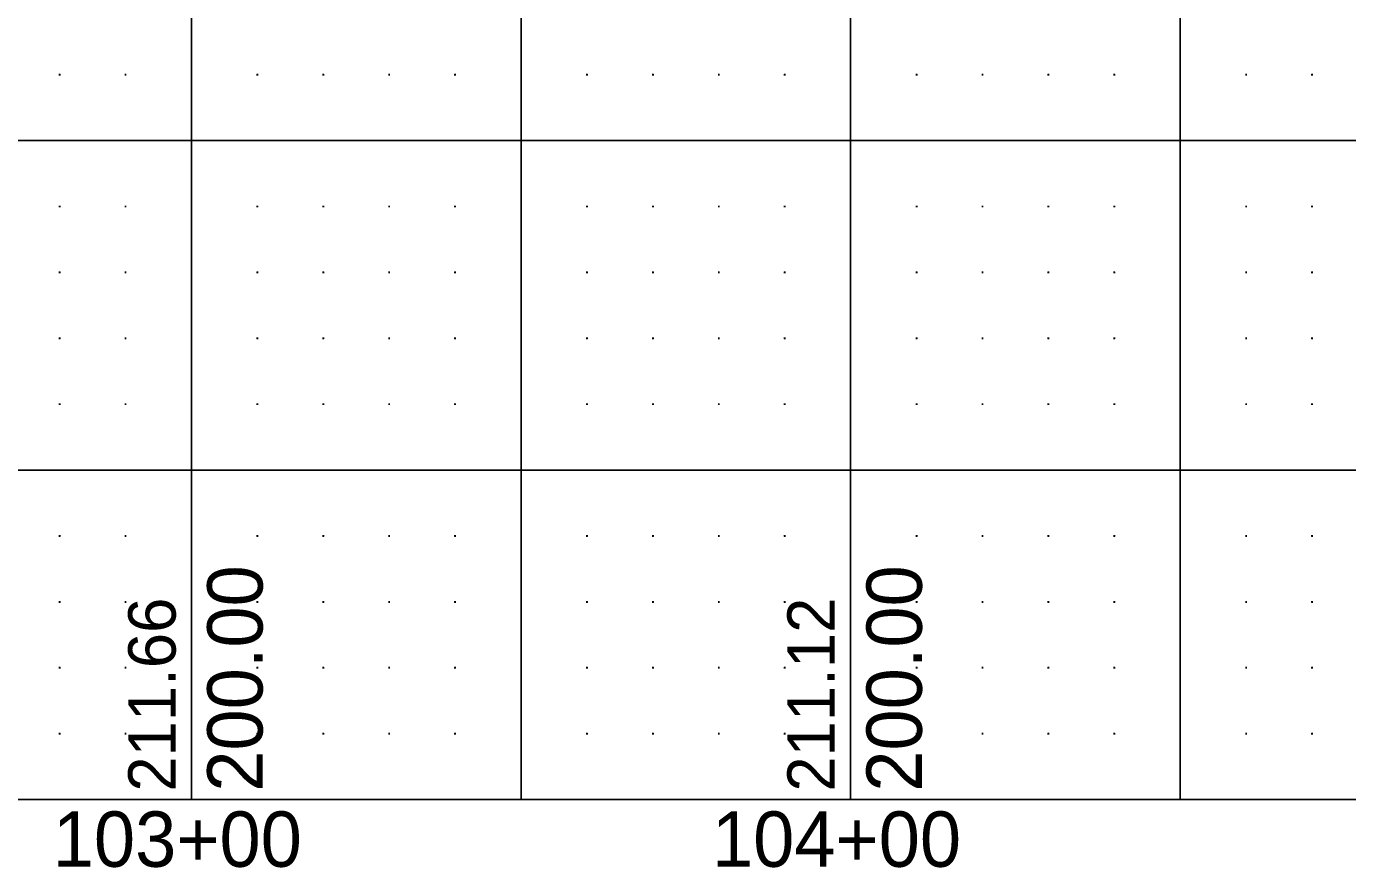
# Model space of a CAD drawing. Extents: x 471 to 2121, y 140 to 650.
# Drawn here: x 911 to 1111.4, y 139.7 to 267.3 of the extents above; entities that cross this region are included whole.
import ezdxf

# ---------------------------------------------------------------- set-up
doc = ezdxf.new("R2010")
doc.units = 0
for name, color, linetype in [('DSN_DRFT_Border Grid', 7, 'Continuous'), ('DSN_RDWY_Prof Annotation', 7, 'Continuous'), ('EX_Profile Annotation', 7, 'Continuous')]:
    doc.layers.add(name, color=color, linetype=linetype)

msp = doc.modelspace()

# ---------------------------------------------------------------- linework, layer by layer
at = {"layer": 'DSN_DRFT_Border Grid'}
for p, q in [((936.06, 150), (936.06, 650)), ((936.06, 150), (936.06, 650)), ((986.06, 150), (986.06, 650)), ((986.06, 150), (986.06, 650)), ((1036.06, 150), (1036.06, 650)), ((1036.06, 150), (1036.06, 650)), ((1086.06, 150), (1086.06, 650)), ((1086.06, 150), (1086.06, 650)), ((916.18, 260), (915.94, 260)), ((916.18, 260), (915.94, 260)), ((916.06, 260.12), (916.06, 259.88)), ((916.06, 260.12), (916.06, 259.88)), ((926.18, 260), (925.94, 260)), ((926.18, 260), (925.94, 260)), ((926.06, 260.12), (926.06, 259.88)), ((926.06, 260.12), (926.06, 259.88)), ((946.18, 260), (945.94, 260)), ((946.18, 260), (945.94, 260)), ((946.06, 260.12), (946.06, 259.88)), ((946.06, 260.12), (946.06, 259.88)), ((956.18, 260), (955.94, 260)), ((956.18, 260), (955.94, 260)), ((956.06, 260.12), (956.06, 259.88)), ((956.06, 260.12), (956.06, 259.88)), ((966.18, 260), (965.94, 260)), ((966.18, 260), (965.94, 260)), ((966.06, 260.12), (966.06, 259.88)), ((966.06, 260.12), (966.06, 259.88)), ((976.18, 260), (975.94, 260)), ((976.18, 260), (975.94, 260)), ((976.06, 260.12), (976.06, 259.88)), ((976.06, 260.12), (976.06, 259.88)), ((996.18, 260), (995.94, 260)), ((996.18, 260), (995.94, 260)), ((996.06, 260.12), (996.06, 259.88)), ((996.06, 260.12), (996.06, 259.88)), ((1006.18, 260), (1005.94, 260)), ((1006.18, 260), (1005.94, 260)), ((1006.06, 260.12), (1006.06, 259.88)), ((1006.06, 260.12), (1006.06, 259.88)), ((1016.18, 260), (1015.94, 260)), ((1016.18, 260), (1015.94, 260)), ((1016.06, 260.12), (1016.06, 259.88)), ((1016.06, 260.12), (1016.06, 259.88)), ((1026.18, 260), (1025.94, 260)), ((1026.18, 260), (1025.94, 260)), ((1026.06, 260.12), (1026.06, 259.88)), ((1026.06, 260.12), (1026.06, 259.88)), ((1046.18, 260), (1045.94, 260)), ((1046.18, 260), (1045.94, 260)), ((1046.06, 260.12), (1046.06, 259.88)), ((1046.06, 260.12), (1046.06, 259.88)), ((1056.18, 260), (1055.94, 260)), ((1056.18, 260), (1055.94, 260)), ((1056.06, 260.12), (1056.06, 259.88)), ((1056.06, 260.12), (1056.06, 259.88)), ((1066.18, 260), (1065.94, 260)), ((1066.18, 260), (1065.94, 260)), ((1066.06, 260.12), (1066.06, 259.88)), ((1066.06, 260.12), (1066.06, 259.88)), ((1076.18, 260), (1075.94, 260)), ((1076.18, 260), (1075.94, 260)), ((1076.06, 260.12), (1076.06, 259.88)), ((1076.06, 260.12), (1076.06, 259.88)), ((1096.18, 260), (1095.94, 260)), ((1096.18, 260), (1095.94, 260)), ((1096.06, 260.12), (1096.06, 259.88)), ((1096.06, 260.12), (1096.06, 259.88)), ((1106.18, 260), (1105.94, 260)), ((1106.18, 260), (1105.94, 260)), ((1106.06, 260.12), (1106.06, 259.88)), ((1106.06, 260.12), (1106.06, 259.88)), ((521.06, 250), (2071.06, 250)), ((521.06, 250), (2071.06, 250)), ((916.18, 240), (915.94, 240)), ((916.18, 240), (915.94, 240)), ((916.06, 240.12), (916.06, 239.88)), ((916.06, 240.12), (916.06, 239.88)), ((926.18, 240), (925.94, 240)), ((926.18, 240), (925.94, 240)), ((926.06, 240.12), (926.06, 239.88)), ((926.06, 240.12), (926.06, 239.88)), ((946.18, 240), (945.94, 240)), ((946.18, 240), (945.94, 240)), ((946.06, 240.12), (946.06, 239.88)), ((946.06, 240.12), (946.06, 239.88)), ((956.18, 240), (955.94, 240)), ((956.18, 240), (955.94, 240)), ((956.06, 240.12), (956.06, 239.88)), ((956.06, 240.12), (956.06, 239.88)), ((966.18, 240), (965.94, 240)), ((966.18, 240), (965.94, 240)), ((966.06, 240.12), (966.06, 239.88)), ((966.06, 240.12), (966.06, 239.88)), ((976.18, 240), (975.94, 240)), ((976.18, 240), (975.94, 240)), ((976.06, 240.12), (976.06, 239.88)), ((976.06, 240.12), (976.06, 239.88)), ((996.18, 240), (995.94, 240)), ((996.18, 240), (995.94, 240)), ((996.06, 240.12), (996.06, 239.88)), ((996.06, 240.12), (996.06, 239.88)), ((1006.18, 240), (1005.94, 240)), ((1006.18, 240), (1005.94, 240)), ((1006.06, 240.12), (1006.06, 239.88)), ((1006.06, 240.12), (1006.06, 239.88)), ((1016.18, 240), (1015.94, 240)), ((1016.18, 240), (1015.94, 240)), ((1016.06, 240.12), (1016.06, 239.88)), ((1016.06, 240.12), (1016.06, 239.88)), ((1026.18, 240), (1025.94, 240)), ((1026.18, 240), (1025.94, 240)), ((1026.06, 240.12), (1026.06, 239.88)), ((1026.06, 240.12), (1026.06, 239.88)), ((1046.18, 240), (1045.94, 240)), ((1046.18, 240), (1045.94, 240)), ((1046.06, 240.12), (1046.06, 239.88)), ((1046.06, 240.12), (1046.06, 239.88)), ((1056.18, 240), (1055.94, 240)), ((1056.18, 240), (1055.94, 240)), ((1056.06, 240.12), (1056.06, 239.88)), ((1056.06, 240.12), (1056.06, 239.88)), ((1066.18, 240), (1065.94, 240)), ((1066.18, 240), (1065.94, 240)), ((1066.06, 240.12), (1066.06, 239.88)), ((1066.06, 240.12), (1066.06, 239.88)), ((1076.18, 240), (1075.94, 240)), ((1076.18, 240), (1075.94, 240)), ((1076.06, 240.12), (1076.06, 239.88)), ((1076.06, 240.12), (1076.06, 239.88)), ((1096.18, 240), (1095.94, 240)), ((1096.18, 240), (1095.94, 240)), ((1096.06, 240.12), (1096.06, 239.88)), ((1096.06, 240.12), (1096.06, 239.88)), ((1106.18, 240), (1105.94, 240)), ((1106.18, 240), (1105.94, 240)), ((1106.06, 240.12), (1106.06, 239.88)), ((1106.06, 240.12), (1106.06, 239.88)), ((916.18, 230), (915.94, 230)), ((916.18, 230), (915.94, 230)), ((916.06, 230.12), (916.06, 229.88)), ((916.06, 230.12), (916.06, 229.88)), ((926.18, 230), (925.94, 230)), ((926.18, 230), (925.94, 230)), ((926.06, 230.12), (926.06, 229.88)), ((926.06, 230.12), (926.06, 229.88)), ((946.18, 230), (945.94, 230)), ((946.18, 230), (945.94, 230)), ((946.06, 230.12), (946.06, 229.88)), ((946.06, 230.12), (946.06, 229.88)), ((956.18, 230), (955.94, 230)), ((956.18, 230), (955.94, 230)), ((956.06, 230.12), (956.06, 229.88)), ((956.06, 230.12), (956.06, 229.88)), ((966.18, 230), (965.94, 230)), ((966.18, 230), (965.94, 230)), ((966.06, 230.12), (966.06, 229.88)), ((966.06, 230.12), (966.06, 229.88)), ((976.18, 230), (975.94, 230)), ((976.18, 230), (975.94, 230)), ((976.06, 230.12), (976.06, 229.88)), ((976.06, 230.12), (976.06, 229.88)), ((996.18, 230), (995.94, 230)), ((996.18, 230), (995.94, 230)), ((996.06, 230.12), (996.06, 229.88)), ((996.06, 230.12), (996.06, 229.88)), ((1006.18, 230), (1005.94, 230)), ((1006.18, 230), (1005.94, 230)), ((1006.06, 230.12), (1006.06, 229.88)), ((1006.06, 230.12), (1006.06, 229.88)), ((1016.18, 230), (1015.94, 230)), ((1016.18, 230), (1015.94, 230)), ((1016.06, 230.12), (1016.06, 229.88)), ((1016.06, 230.12), (1016.06, 229.88)), ((1026.18, 230), (1025.94, 230)), ((1026.18, 230), (1025.94, 230)), ((1026.06, 230.12), (1026.06, 229.88)), ((1026.06, 230.12), (1026.06, 229.88)), ((1046.18, 230), (1045.94, 230)), ((1046.18, 230), (1045.94, 230)), ((1046.06, 230.12), (1046.06, 229.88)), ((1046.06, 230.12), (1046.06, 229.88)), ((1056.18, 230), (1055.94, 230)), ((1056.18, 230), (1055.94, 230)), ((1056.06, 230.12), (1056.06, 229.88)), ((1056.06, 230.12), (1056.06, 229.88)), ((1066.18, 230), (1065.94, 230)), ((1066.18, 230), (1065.94, 230)), ((1066.06, 230.12), (1066.06, 229.88)), ((1066.06, 230.12), (1066.06, 229.88)), ((1076.18, 230), (1075.94, 230)), ((1076.18, 230), (1075.94, 230)), ((1076.06, 230.12), (1076.06, 229.88)), ((1076.06, 230.12), (1076.06, 229.88)), ((1096.18, 230), (1095.94, 230)), ((1096.18, 230), (1095.94, 230)), ((1096.06, 230.12), (1096.06, 229.88)), ((1096.06, 230.12), (1096.06, 229.88)), ((1106.18, 230), (1105.94, 230)), ((1106.18, 230), (1105.94, 230)), ((1106.06, 230.12), (1106.06, 229.88)), ((1106.06, 230.12), (1106.06, 229.88)), ((916.18, 220), (915.94, 220)), ((916.18, 220), (915.94, 220)), ((916.06, 220.12), (916.06, 219.88)), ((916.06, 220.12), (916.06, 219.88)), ((926.18, 220), (925.94, 220)), ((926.18, 220), (925.94, 220)), ((926.06, 220.12), (926.06, 219.88)), ((926.06, 220.12), (926.06, 219.88)), ((946.18, 220), (945.94, 220)), ((946.18, 220), (945.94, 220)), ((946.06, 220.12), (946.06, 219.88)), ((946.06, 220.12), (946.06, 219.88)), ((956.18, 220), (955.94, 220)), ((956.18, 220), (955.94, 220)), ((956.06, 220.12), (956.06, 219.88)), ((956.06, 220.12), (956.06, 219.88)), ((966.18, 220), (965.94, 220)), ((966.18, 220), (965.94, 220)), ((966.06, 220.12), (966.06, 219.88)), ((966.06, 220.12), (966.06, 219.88)), ((976.18, 220), (975.94, 220)), ((976.18, 220), (975.94, 220)), ((976.06, 220.12), (976.06, 219.88)), ((976.06, 220.12), (976.06, 219.88)), ((996.18, 220), (995.94, 220)), ((996.18, 220), (995.94, 220)), ((996.06, 220.12), (996.06, 219.88)), ((996.06, 220.12), (996.06, 219.88)), ((1006.18, 220), (1005.94, 220)), ((1006.18, 220), (1005.94, 220)), ((1006.06, 220.12), (1006.06, 219.88)), ((1006.06, 220.12), (1006.06, 219.88)), ((1016.18, 220), (1015.94, 220)), ((1016.18, 220), (1015.94, 220)), ((1016.06, 220.12), (1016.06, 219.88)), ((1016.06, 220.12), (1016.06, 219.88)), ((1026.18, 220), (1025.94, 220)), ((1026.18, 220), (1025.94, 220)), ((1026.06, 220.12), (1026.06, 219.88)), ((1026.06, 220.12), (1026.06, 219.88)), ((1046.18, 220), (1045.94, 220)), ((1046.18, 220), (1045.94, 220)), ((1046.06, 220.12), (1046.06, 219.88)), ((1046.06, 220.12), (1046.06, 219.88)), ((1056.18, 220), (1055.94, 220)), ((1056.18, 220), (1055.94, 220)), ((1056.06, 220.12), (1056.06, 219.88)), ((1056.06, 220.12), (1056.06, 219.88)), ((1066.18, 220), (1065.94, 220)), ((1066.18, 220), (1065.94, 220)), ((1066.06, 220.12), (1066.06, 219.88)), ((1066.06, 220.12), (1066.06, 219.88)), ((1076.18, 220), (1075.94, 220)), ((1076.18, 220), (1075.94, 220)), ((1076.06, 220.12), (1076.06, 219.88)), ((1076.06, 220.12), (1076.06, 219.88)), ((1096.18, 220), (1095.94, 220)), ((1096.18, 220), (1095.94, 220)), ((1096.06, 220.12), (1096.06, 219.88)), ((1096.06, 220.12), (1096.06, 219.88)), ((1106.18, 220), (1105.94, 220)), ((1106.18, 220), (1105.94, 220)), ((1106.06, 220.12), (1106.06, 219.88)), ((1106.06, 220.12), (1106.06, 219.88)), ((916.18, 210), (915.94, 210)), ((916.18, 210), (915.94, 210)), ((916.06, 210.12), (916.06, 209.88)), ((916.06, 210.12), (916.06, 209.88)), ((926.18, 210), (925.94, 210)), ((926.18, 210), (925.94, 210)), ((926.06, 210.12), (926.06, 209.88)), ((926.06, 210.12), (926.06, 209.88)), ((946.18, 210), (945.94, 210)), ((946.18, 210), (945.94, 210)), ((946.06, 210.12), (946.06, 209.88)), ((946.06, 210.12), (946.06, 209.88)), ((956.18, 210), (955.94, 210)), ((956.18, 210), (955.94, 210)), ((956.06, 210.12), (956.06, 209.88)), ((956.06, 210.12), (956.06, 209.88)), ((966.18, 210), (965.94, 210)), ((966.18, 210), (965.94, 210)), ((966.06, 210.12), (966.06, 209.88)), ((966.06, 210.12), (966.06, 209.88)), ((976.18, 210), (975.94, 210)), ((976.18, 210), (975.94, 210)), ((976.06, 210.12), (976.06, 209.88)), ((976.06, 210.12), (976.06, 209.88)), ((996.18, 210), (995.94, 210)), ((996.18, 210), (995.94, 210)), ((996.06, 210.12), (996.06, 209.88)), ((996.06, 210.12), (996.06, 209.88)), ((1006.18, 210), (1005.94, 210)), ((1006.18, 210), (1005.94, 210)), ((1006.06, 210.12), (1006.06, 209.88)), ((1006.06, 210.12), (1006.06, 209.88)), ((1016.18, 210), (1015.94, 210)), ((1016.18, 210), (1015.94, 210)), ((1016.06, 210.12), (1016.06, 209.88)), ((1016.06, 210.12), (1016.06, 209.88)), ((1026.18, 210), (1025.94, 210)), ((1026.18, 210), (1025.94, 210)), ((1026.06, 210.12), (1026.06, 209.88)), ((1026.06, 210.12), (1026.06, 209.88)), ((1046.18, 210), (1045.94, 210)), ((1046.18, 210), (1045.94, 210)), ((1046.06, 210.12), (1046.06, 209.88)), ((1046.06, 210.12), (1046.06, 209.88)), ((1056.18, 210), (1055.94, 210)), ((1056.18, 210), (1055.94, 210)), ((1056.06, 210.12), (1056.06, 209.88)), ((1056.06, 210.12), (1056.06, 209.88)), ((1066.18, 210), (1065.94, 210)), ((1066.18, 210), (1065.94, 210)), ((1066.06, 210.12), (1066.06, 209.88)), ((1066.06, 210.12), (1066.06, 209.88)), ((1076.18, 210), (1075.94, 210)), ((1076.18, 210), (1075.94, 210)), ((1076.06, 210.12), (1076.06, 209.88)), ((1076.06, 210.12), (1076.06, 209.88)), ((1096.18, 210), (1095.94, 210)), ((1096.18, 210), (1095.94, 210)), ((1096.06, 210.12), (1096.06, 209.88)), ((1096.06, 210.12), (1096.06, 209.88)), ((1106.18, 210), (1105.94, 210)), ((1106.18, 210), (1105.94, 210)), ((1106.06, 210.12), (1106.06, 209.88)), ((1106.06, 210.12), (1106.06, 209.88)), ((521.06, 200), (2071.06, 200)), ((521.06, 200), (2071.06, 200)), ((916.18, 190), (915.94, 190)), ((916.18, 190), (915.94, 190)), ((916.06, 190.12), (916.06, 189.88)), ((916.06, 190.12), (916.06, 189.88)), ((926.18, 190), (925.94, 190)), ((926.18, 190), (925.94, 190)), ((926.06, 190.12), (926.06, 189.88)), ((926.06, 190.12), (926.06, 189.88)), ((946.18, 190), (945.94, 190)), ((946.18, 190), (945.94, 190)), ((946.06, 190.12), (946.06, 189.88)), ((946.06, 190.12), (946.06, 189.88)), ((956.18, 190), (955.94, 190)), ((956.18, 190), (955.94, 190)), ((956.06, 190.12), (956.06, 189.88)), ((956.06, 190.12), (956.06, 189.88)), ((966.18, 190), (965.94, 190)), ((966.18, 190), (965.94, 190)), ((966.06, 190.12), (966.06, 189.88)), ((966.06, 190.12), (966.06, 189.88)), ((976.18, 190), (975.94, 190)), ((976.18, 190), (975.94, 190)), ((976.06, 190.12), (976.06, 189.88)), ((976.06, 190.12), (976.06, 189.88)), ((996.18, 190), (995.94, 190)), ((996.18, 190), (995.94, 190)), ((996.06, 190.12), (996.06, 189.88)), ((996.06, 190.12), (996.06, 189.88)), ((1006.18, 190), (1005.94, 190)), ((1006.18, 190), (1005.94, 190)), ((1006.06, 190.12), (1006.06, 189.88)), ((1006.06, 190.12), (1006.06, 189.88)), ((1016.18, 190), (1015.94, 190)), ((1016.18, 190), (1015.94, 190)), ((1016.06, 190.12), (1016.06, 189.88)), ((1016.06, 190.12), (1016.06, 189.88)), ((1026.18, 190), (1025.94, 190)), ((1026.18, 190), (1025.94, 190)), ((1026.06, 190.12), (1026.06, 189.88)), ((1026.06, 190.12), (1026.06, 189.88)), ((1046.18, 190), (1045.94, 190)), ((1046.18, 190), (1045.94, 190)), ((1046.06, 190.12), (1046.06, 189.88)), ((1046.06, 190.12), (1046.06, 189.88)), ((1056.18, 190), (1055.94, 190)), ((1056.18, 190), (1055.94, 190)), ((1056.06, 190.12), (1056.06, 189.88)), ((1056.06, 190.12), (1056.06, 189.88)), ((1066.18, 190), (1065.94, 190)), ((1066.18, 190), (1065.94, 190)), ((1066.06, 190.12), (1066.06, 189.88)), ((1066.06, 190.12), (1066.06, 189.88)), ((1076.18, 190), (1075.94, 190)), ((1076.18, 190), (1075.94, 190)), ((1076.06, 190.12), (1076.06, 189.88)), ((1076.06, 190.12), (1076.06, 189.88)), ((1096.18, 190), (1095.94, 190)), ((1096.18, 190), (1095.94, 190)), ((1096.06, 190.12), (1096.06, 189.88)), ((1096.06, 190.12), (1096.06, 189.88)), ((1106.18, 190), (1105.94, 190)), ((1106.18, 190), (1105.94, 190)), ((1106.06, 190.12), (1106.06, 189.88)), ((1106.06, 190.12), (1106.06, 189.88)), ((916.18, 180), (915.94, 180)), ((916.18, 180), (915.94, 180)), ((916.06, 180.12), (916.06, 179.88)), ((916.06, 180.12), (916.06, 179.88)), ((926.18, 180), (925.94, 180)), ((926.18, 180), (925.94, 180)), ((926.06, 180.12), (926.06, 179.88)), ((926.06, 180.12), (926.06, 179.88)), ((946.18, 180), (945.94, 180)), ((946.18, 180), (945.94, 180)), ((946.06, 180.12), (946.06, 179.88)), ((946.06, 180.12), (946.06, 179.88)), ((956.18, 180), (955.94, 180)), ((956.18, 180), (955.94, 180)), ((956.06, 180.12), (956.06, 179.88)), ((956.06, 180.12), (956.06, 179.88)), ((966.18, 180), (965.94, 180)), ((966.18, 180), (965.94, 180)), ((966.06, 180.12), (966.06, 179.88)), ((966.06, 180.12), (966.06, 179.88)), ((976.18, 180), (975.94, 180)), ((976.18, 180), (975.94, 180)), ((976.06, 180.12), (976.06, 179.88)), ((976.06, 180.12), (976.06, 179.88)), ((996.18, 180), (995.94, 180)), ((996.18, 180), (995.94, 180)), ((996.06, 180.12), (996.06, 179.88)), ((996.06, 180.12), (996.06, 179.88)), ((1006.18, 180), (1005.94, 180)), ((1006.18, 180), (1005.94, 180)), ((1006.06, 180.12), (1006.06, 179.88)), ((1006.06, 180.12), (1006.06, 179.88)), ((1016.18, 180), (1015.94, 180)), ((1016.18, 180), (1015.94, 180)), ((1016.06, 180.12), (1016.06, 179.88)), ((1016.06, 180.12), (1016.06, 179.88)), ((1026.18, 180), (1025.94, 180)), ((1026.18, 180), (1025.94, 180)), ((1026.06, 180.12), (1026.06, 179.88)), ((1026.06, 180.12), (1026.06, 179.88)), ((1046.18, 180), (1045.94, 180)), ((1046.18, 180), (1045.94, 180)), ((1046.06, 180.12), (1046.06, 179.88)), ((1046.06, 180.12), (1046.06, 179.88)), ((1056.18, 180), (1055.94, 180)), ((1056.18, 180), (1055.94, 180)), ((1056.06, 180.12), (1056.06, 179.88)), ((1056.06, 180.12), (1056.06, 179.88)), ((1066.18, 180), (1065.94, 180)), ((1066.18, 180), (1065.94, 180)), ((1066.06, 180.12), (1066.06, 179.88)), ((1066.06, 180.12), (1066.06, 179.88)), ((1076.18, 180), (1075.94, 180)), ((1076.18, 180), (1075.94, 180)), ((1076.06, 180.12), (1076.06, 179.88)), ((1076.06, 180.12), (1076.06, 179.88)), ((1096.18, 180), (1095.94, 180)), ((1096.18, 180), (1095.94, 180)), ((1096.06, 180.12), (1096.06, 179.88)), ((1096.06, 180.12), (1096.06, 179.88)), ((1106.18, 180), (1105.94, 180)), ((1106.18, 180), (1105.94, 180)), ((1106.06, 180.12), (1106.06, 179.88)), ((1106.06, 180.12), (1106.06, 179.88)), ((916.18, 170), (915.94, 170)), ((916.18, 170), (915.94, 170)), ((916.06, 170.12), (916.06, 169.88)), ((916.06, 170.12), (916.06, 169.88)), ((926.18, 170), (925.94, 170)), ((926.18, 170), (925.94, 170)), ((926.06, 170.12), (926.06, 169.88)), ((926.06, 170.12), (926.06, 169.88)), ((946.18, 170), (945.94, 170)), ((946.18, 170), (945.94, 170)), ((946.06, 170.12), (946.06, 169.88)), ((946.06, 170.12), (946.06, 169.88)), ((956.18, 170), (955.94, 170)), ((956.18, 170), (955.94, 170)), ((956.06, 170.12), (956.06, 169.88)), ((956.06, 170.12), (956.06, 169.88)), ((966.18, 170), (965.94, 170)), ((966.18, 170), (965.94, 170)), ((966.06, 170.12), (966.06, 169.88)), ((966.06, 170.12), (966.06, 169.88)), ((976.18, 170), (975.94, 170)), ((976.18, 170), (975.94, 170)), ((976.06, 170.12), (976.06, 169.88)), ((976.06, 170.12), (976.06, 169.88)), ((996.18, 170), (995.94, 170)), ((996.18, 170), (995.94, 170)), ((996.06, 170.12), (996.06, 169.88)), ((996.06, 170.12), (996.06, 169.88)), ((1006.18, 170), (1005.94, 170)), ((1006.18, 170), (1005.94, 170)), ((1006.06, 170.12), (1006.06, 169.88)), ((1006.06, 170.12), (1006.06, 169.88)), ((1016.18, 170), (1015.94, 170)), ((1016.18, 170), (1015.94, 170)), ((1016.06, 170.12), (1016.06, 169.88)), ((1016.06, 170.12), (1016.06, 169.88)), ((1026.18, 170), (1025.94, 170)), ((1026.18, 170), (1025.94, 170)), ((1026.06, 170.12), (1026.06, 169.88)), ((1026.06, 170.12), (1026.06, 169.88)), ((1046.18, 170), (1045.94, 170)), ((1046.18, 170), (1045.94, 170)), ((1046.06, 170.12), (1046.06, 169.88)), ((1046.06, 170.12), (1046.06, 169.88)), ((1056.18, 170), (1055.94, 170)), ((1056.18, 170), (1055.94, 170)), ((1056.06, 170.12), (1056.06, 169.88)), ((1056.06, 170.12), (1056.06, 169.88)), ((1066.18, 170), (1065.94, 170)), ((1066.18, 170), (1065.94, 170)), ((1066.06, 170.12), (1066.06, 169.88)), ((1066.06, 170.12), (1066.06, 169.88)), ((1076.18, 170), (1075.94, 170)), ((1076.18, 170), (1075.94, 170)), ((1076.06, 170.12), (1076.06, 169.88)), ((1076.06, 170.12), (1076.06, 169.88)), ((1096.18, 170), (1095.94, 170)), ((1096.18, 170), (1095.94, 170)), ((1096.06, 170.12), (1096.06, 169.88)), ((1096.06, 170.12), (1096.06, 169.88)), ((1106.18, 170), (1105.94, 170)), ((1106.18, 170), (1105.94, 170)), ((1106.06, 170.12), (1106.06, 169.88)), ((1106.06, 170.12), (1106.06, 169.88)), ((916.18, 160), (915.94, 160)), ((916.18, 160), (915.94, 160)), ((916.06, 160.12), (916.06, 159.88)), ((916.06, 160.12), (916.06, 159.88)), ((926.18, 160), (925.94, 160)), ((926.18, 160), (925.94, 160)), ((926.06, 160.12), (926.06, 159.88)), ((926.06, 160.12), (926.06, 159.88)), ((946.18, 160), (945.94, 160)), ((946.18, 160), (945.94, 160)), ((946.06, 160.12), (946.06, 159.88)), ((946.06, 160.12), (946.06, 159.88)), ((956.18, 160), (955.94, 160)), ((956.18, 160), (955.94, 160)), ((956.06, 160.12), (956.06, 159.88)), ((956.06, 160.12), (956.06, 159.88)), ((966.18, 160), (965.94, 160)), ((966.18, 160), (965.94, 160)), ((966.06, 160.12), (966.06, 159.88)), ((966.06, 160.12), (966.06, 159.88)), ((976.18, 160), (975.94, 160)), ((976.18, 160), (975.94, 160)), ((976.06, 160.12), (976.06, 159.88)), ((976.06, 160.12), (976.06, 159.88)), ((996.18, 160), (995.94, 160)), ((996.18, 160), (995.94, 160)), ((996.06, 160.12), (996.06, 159.88)), ((996.06, 160.12), (996.06, 159.88)), ((1006.18, 160), (1005.94, 160)), ((1006.18, 160), (1005.94, 160)), ((1006.06, 160.12), (1006.06, 159.88)), ((1006.06, 160.12), (1006.06, 159.88)), ((1016.18, 160), (1015.94, 160)), ((1016.18, 160), (1015.94, 160)), ((1016.06, 160.12), (1016.06, 159.88)), ((1016.06, 160.12), (1016.06, 159.88)), ((1026.18, 160), (1025.94, 160)), ((1026.18, 160), (1025.94, 160)), ((1026.06, 160.12), (1026.06, 159.88)), ((1026.06, 160.12), (1026.06, 159.88)), ((1046.18, 160), (1045.94, 160)), ((1046.18, 160), (1045.94, 160)), ((1046.06, 160.12), (1046.06, 159.88)), ((1046.06, 160.12), (1046.06, 159.88)), ((1056.18, 160), (1055.94, 160)), ((1056.18, 160), (1055.94, 160)), ((1056.06, 160.12), (1056.06, 159.88)), ((1056.06, 160.12), (1056.06, 159.88)), ((1066.18, 160), (1065.94, 160)), ((1066.18, 160), (1065.94, 160)), ((1066.06, 160.12), (1066.06, 159.88)), ((1066.06, 160.12), (1066.06, 159.88)), ((1076.18, 160), (1075.94, 160)), ((1076.18, 160), (1075.94, 160)), ((1076.06, 160.12), (1076.06, 159.88)), ((1076.06, 160.12), (1076.06, 159.88)), ((1096.18, 160), (1095.94, 160)), ((1096.18, 160), (1095.94, 160)), ((1096.06, 160.12), (1096.06, 159.88)), ((1096.06, 160.12), (1096.06, 159.88)), ((1106.18, 160), (1105.94, 160)), ((1106.18, 160), (1105.94, 160)), ((1106.06, 160.12), (1106.06, 159.88)), ((1106.06, 160.12), (1106.06, 159.88)), ((521.06, 150), (2071.06, 150)), ((521.06, 150), (2071.06, 150))]:
    msp.add_line(p, q, dxfattribs=at)

# ---------------------------------------------------------------- texts
at = {"layer": 'DSN_RDWY_Prof Annotation'}
for p in [(946.86, 151.2), (1046.86, 151.2)]:
    msp.add_text('200.00', height=8.4, rotation=90, dxfattribs=at).set_placement(p)
for s, p in [('103+00', (915.02, 139.8)), ('103+00', (915.02, 139.8)), ('104+00', (1015.02, 139.8)), ('104+00', (1015.02, 139.8))]:
    msp.add_text(s, height=8.4, dxfattribs=at).set_placement(p)
at = {"layer": 'EX_Profile Annotation'}
for s, p in [('211.66', (933.67, 151.2)), ('211.12', (1033.66, 151.2))]:
    msp.add_text(s, height=7.2, rotation=90, dxfattribs=at).set_placement(p)

doc.saveas('drawing.dxf')
